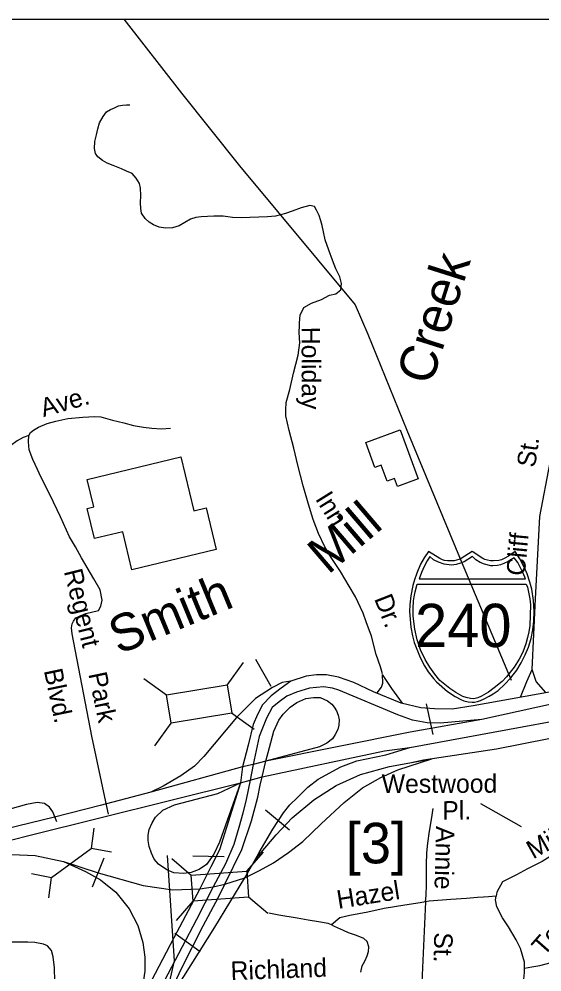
# Model space of a CAD drawing. Extents: x 925297 to 940193, y 663541 to 689899.
# Drawn here: x 929084 to 929507, y 688730 to 689501 of the extents above; entities that cross this region are included whole.
import ezdxf

# ---------------------------------------------------------------- set-up
doc = ezdxf.new("R2010")
doc.units = 0
doc.layers.add('Default', color=7, linetype='Continuous')
doc.layers.add('Sheet Title CELL', color=7, linetype='Continuous')

msp = doc.modelspace()

# ---------------------------------------------------------------- linework, layer by layer
at = {"layer": 'Default'}
for p, q in [((929252.05, 688962.28), (929265.27, 688980.66)), ((929275.13, 688983.38), (929287.52, 688961.33)), ((929184.73, 688967.62), (929203.11, 688954.4)), ((929413.23, 688947.08), (929418.64, 688922.38)), ((929255.7, 688939.94), (929274.07, 688926.72)), ((929193.62, 688913.17), (929206.84, 688931.55)), ((929156.03, 688857.77), (929154.68, 688864.04)), ((929283.17, 688861.25), (929302.69, 688845.17)), ((929144.14, 688846.59), (929142.01, 688830.07)), ((929109.96, 688806.69), (929142.01, 688830.07)), ((929158.39, 688827.05), (929142.01, 688830.07)), ((929267.97, 688811.6), (929281.42, 688827.17)), ((929152.28, 688822.13), (929142.84, 688798.67)), ((929207.44, 688821.86), (929223.01, 688808.41)), ((929224.33, 688824.24), (929249.61, 688823.5)), ((929093.58, 688809.71), (929109.96, 688806.69)), ((929107.83, 688790.17), (929109.96, 688806.69)), ((929229.97, 688797.34), (929240.68, 688799)), ((929211.1, 688771.84), (929224.55, 688787.41)), ((929269.47, 688791.08), (929285.05, 688777.63)), ((929412.85, 688786.82), (929409.51, 688715.72)), ((929209.72, 688761.43), (929230.21, 688746.61))]:
    msp.add_line(p, q, dxfattribs=at)
for points in [[(929168.36, 689501.34), (929215.26, 689441.28), (929262.13, 689382.59), (929355.71, 689269.93), (929365.93, 689246.36), (929397.72, 689168.54), (929441.55, 689062.65), (929482.15, 688966.28)], [(929378.04, 688971.41), (929376.26, 688977.04), (929372.78, 688987.01), (929369.08, 689001.83), (929364.67, 689013.56), (929362.13, 689020.41), (929356.02, 689033.71), (929350.94, 689042.25), (929343.9, 689054.19), (929336.31, 689065.66), (929331.23, 689074.32), (929326.05, 689085.09), (929321.75, 689096.33), (929317.59, 689109.43), (929313.73, 689123.64), (929309.48, 689140.37), (929305.99, 689154.01), (929302.43, 689168.45), (929299.51, 689180.23), (929299.72, 689185.02), (929299.99, 689190.97), (929302.79, 689201.42), (929305.74, 689214.77), (929309.71, 689229.41), (929310.91, 689239.34), (929310.41, 689247.71), (929310.57, 689253.41), (929310.63, 689255.43), (929311.3, 689261.76), (929314.3, 689267.78), (929320.31, 689271.28), (929328.45, 689274.3), (929335.11, 689277.82), (929340.19, 689279.06), (929344.25, 689282.11), (929344.75, 689287.2), (929343.23, 689292.63), (929340.24, 689299.18), (929337.45, 689306.19), (929334.42, 689314.17), (929331.4, 689322.65), (929330.01, 689329.2), (929329.08, 689334.15), (929327.99, 689338.13), (929326.6, 689342.44), (929324.57, 689346.81), (929322.91, 689349.53), (929319.03, 689350.55), (929312.06, 689348.53), (929304.71, 689345.84), (929299.49, 689344.09), (929291.28, 689341.85), (929284.87, 689341.31), (929263.56, 689340.46), (929256.33, 689340.87), (929248.95, 689341.83), (929241.46, 689341.87), (929230.94, 689341.26), (929226.71, 689340.63), (929222.41, 689339.34), (929213.21, 689334.08), (929207.82, 689332.3), (929202.1, 689332.12), (929196.96, 689332.98), (929192.58, 689334.69), (929189.07, 689337.04), (929185.62, 689339.88), (929182.85, 689344.2), (929182.14, 689348.06), (929181.96, 689352.72), (929182.18, 689358.63), (929181.85, 689364.56), (929181.2, 689368.28), (929178.49, 689372.48), (929175.16, 689376.38), (929170.58, 689378.13), (929166.58, 689380.14), (929159.88, 689382.91), (929154.91, 689384.59), (929151.29, 689386.82), (929147.4, 689389.82), (929145.5, 689392.59), (929144.8, 689396.71), (929144.87, 689402.23), (929144.88, 689402.23), (929146.21, 689407.72), (929147.31, 689412.38), (929148.8, 689417.24), (929151.66, 689422.55), (929154.53, 689426.37), (929157.75, 689428.1), (929160.8, 689429.59), (929164.16, 689430.98), (929167.39, 689431.63), (929170.63, 689431.8), (929173.36, 689431.84)], [(929499.18, 688974.92), (929501.93, 689032.24), (929505.34, 689098.74), (929513.58, 689142.43), (929524.71, 689167.77), (929536.62, 689179.25), (929545.81, 689184.49), (929556.93, 689190.11)], [(929091.59, 689164.22), (929092.87, 689166.73), (929095.19, 689168.5), (929099.4, 689170.93), (929106.48, 689173.92), (929113.34, 689176.02), (929123.07, 689178.12), (929135.35, 689179.12), (929144.97, 689179.67), (929149.84, 689179.34), (929159.25, 689176.79), (929168.54, 689174.47), (929176.17, 689172.48), (929184.36, 689171.04), (929191.11, 689170.16), (929198.96, 689169.72), (929206.26, 689170.16)], [(929091.59, 689164.22), (929086.94, 689162.68), (929082.03, 689159.98), (929076.97, 689156.13), (929070.78, 689150.36), (929062.73, 689145.3), (929053.32, 689140.42), (929045.08, 689137.59), (929039.9, 689135.71)], [(929154.68, 688864.04), (929142.45, 688920.9), (929126.58, 689003.68), (929126.06, 689008.76), (929126.5, 689011.85), (929127.61, 689013.96), (929129.49, 689016.72), (929132.12, 689017.89), (929137.68, 689020.15), (929147.85, 689022.69), (929149.85, 689026.12), (929150.84, 689030.99), (929149.32, 689039.3), (929144.09, 689048.25), (929134.14, 689065.31), (929129.28, 689074.14), (929124.51, 689082.32), (929117.21, 689098.58), (929108.8, 689115.95), (929101.17, 689130.88), (929098.51, 689136.75), (929094.75, 689144.93), (929091.76, 689152.79), (929091.32, 689159.2), (929091.59, 689164.22)], [(929489.63, 688952.5), (929494.84, 688965.1), (929499.18, 688974.92)], [(929510.24, 688956.45), (929502.37, 688965.24), (929499.18, 688974.92)], [(929303.7, 688965.55), (929296.72, 688964.48), (929288.77, 688960.39), (929275.02, 688951.36), (929265.56, 688942.11), (929259.76, 688936.09), (929233.11, 688904.49), (929225.7, 688896.75), (929214.64, 688888.79), (929200.35, 688880.41), (929190.42, 688875.58)], [(929303.7, 688965.55), (929295.75, 688959.75), (929287.69, 688953.62), (929280.82, 688946.31), (929276.73, 688938.57), (929273.3, 688930.29), (929269, 688913.73), (929264.67, 688896.19)], [(929606.92, 688969.72), (929604.98, 688969.65), (929573.53, 688965.31), (929525.09, 688958.79), (929451.35, 688945.41), (929434.36, 688942.88), (929419.9, 688943.06), (929409.05, 688943.78), (929392.97, 688947.58), (929370.73, 688956.81), (929354.83, 688964.4), (929342.38, 688968.78), (929332.5, 688970.5), (929324.54, 688970.71), (929316.06, 688969.53), (929303.7, 688965.55)], [(929373.49, 688956.02), (929377.22, 688960.54), (929378.21, 688963.79), (929378.04, 688970.98)], [(929394.2, 688947.64), (929385.38, 688959.68), (929378.04, 688970.98)], [(929621.29, 688970.27), (929458.27, 688934.53)], [(929458.27, 688934.53), (929424.65, 688931.46), (929414.16, 688931.64), (929402.24, 688933.99), (929390.31, 688938.33), (929342.59, 688958.23), (929337.48, 688959.88), (929330.12, 688960.94), (929318.86, 688959.7), (929308.38, 688956.62), (929300.41, 688953.38), (929294.34, 688948.83), (929288.63, 688944.1), (929283.92, 688935.6), (929277.91, 688920.75), (929273.08, 688898.02)], [(929400.16, 688911.9), (929605.34, 688949.58), (929647.6, 688958.63)], [(929283.32, 688900.7), (929286.35, 688911.85), (929290.01, 688925.04), (929293.91, 688933.83), (929297.57, 688938.83), (929303.06, 688944.45), (929308.55, 688948.11), (929315.87, 688951.41), (929321.97, 688952.38), (929327.46, 688952.14), (929333.32, 688949.48)], [(929333.32, 688949.48), (929336.85, 688946.89), (929338.8, 688944.33), (929340.76, 688941.52), (929342.1, 688937.98), (929342.71, 688934.19), (929342.46, 688929.92), (929341.73, 688926.38), (929339.66, 688922.35), (929337.34, 688918.81), (929332.95, 688915.39), (929326.85, 688912.46), (929283.32, 688900.7)], [(929458.27, 688934.53), (929400.26, 688924.11), (929283.32, 688900.7)], [(929402.43, 688899.91), (929411.12, 688901.71), (929470.24, 688910.78), (929534.53, 688923.46), (929536.63, 688924.03)], [(929275.08, 688821.48), (929278.13, 688826.84), (929289.16, 688845.73), (929297.7, 688859.03), (929302.77, 688865.51), (929309.12, 688871.36), (929317.46, 688879.71), (929325.8, 688886.26), (929344.05, 688896.14), (929357.21, 688900.97), (929380.51, 688905.89), (929400.16, 688911.9)], [(929280.5, 688888.12), (929379.41, 688908.98), (929400.16, 688911.9)], [(929266.51, 688806.41), (929278.27, 688812.23), (929289.59, 688818.49), (929301.8, 688826.83), (929313.41, 688835.77), (929328.31, 688850.08), (929346.78, 688867.36), (929361.67, 688879.28), (929376.59, 688887.63), (929390.46, 688893.74), (929417.93, 688902.6)], [(929275.08, 688821.48), (929291.8, 688841.19), (929304.87, 688854.94), (929322.3, 688869.36), (929340.4, 688881.1), (929360.17, 688889.82), (929383.62, 688896.33), (929417.93, 688902.6)], [(929264.67, 688896.19), (929190.42, 688875.58)], [(929264.67, 688896.19), (929262.95, 688883.29)], [(929273.08, 688898.02), (929264.67, 688896.19)], [(929273.08, 688898.02), (929270.84, 688885.3)], [(929283.32, 688900.7), (929273.08, 688898.02)], [(929280.5, 688888.12), (929283.32, 688900.7)], [(929250.18, 688801.15), (929264.03, 688829.19), (929271.82, 688852.34), (929276.83, 688871.74), (929278.91, 688881.31), (929280.5, 688888.12)], [(929270.84, 688885.3), (929280.5, 688888.12)], [(929027.74, 688824.35), (929091.51, 688840.54), (929262.95, 688883.29)], [(929262.95, 688883.29), (929245.94, 688835.24), (929241.44, 688825.45), (929235.5, 688817.13), (929229.56, 688812.97), (929223.02, 688810.59), (929216.69, 688809.8), (929208.96, 688810.4), (929203.22, 688812.77), (929196.49, 688817.33), (929193.12, 688821.49), (929190.78, 688826.24), (929188.87, 688831.77), (929188.23, 688836.45), (929188.23, 688840.92), (929188.87, 688845.39), (929191.34, 688850.82), (929194.11, 688855.37), (929200.05, 688861.12), (929209.35, 688865.39), (929244.57, 688874.69), (929262.95, 688883.29)], [(929262.95, 688883.29), (929245.85, 688828.9), (929239.02, 688815.13), (929229.97, 688797.34)], [(929270.84, 688885.3), (929267.43, 688869.63), (929264.84, 688858.67), (929261.65, 688847.01), (929257.65, 688833.35), (929250.79, 688817.68), (929240.68, 688799)], [(929262.95, 688883.29), (929270.84, 688885.3)], [(929190.42, 688875.58), (929149.29, 688864.98), (929112.36, 688855.44), (929052.19, 688840.84), (929001.1, 688828.77), (928863.79, 688792.71), (928727.82, 688759.49), (928686.82, 688753.06), (928655.56, 688749.51), (928625.66, 688747.58), (928584.13, 688746.27), (928553.43, 688746.59)], [(929114.22, 688851.67), (929110.87, 688859.75), (929108.23, 688863.64), (929104.25, 688866.47), (929098.22, 688867.29), (929089.64, 688865.56), (929082.78, 688863.79), (929076.09, 688861.93), (929072.45, 688860.92)], [(929457.14, 688866.48), (929490.26, 688847.89)], [(929581.65, 688866.44), (929580.92, 688866.03), (929568.37, 688858.13), (929557.96, 688851.93), (929545.47, 688843.03), (929541.21, 688840.61), (929535.96, 688837.63), (929527.86, 688832.08), (929521.92, 688828.59), (929517.23, 688825.82), (929507.25, 688819.65), (929495.21, 688813.72), (929486.39, 688808.82), (929474.98, 688803.19), (929470.63, 688794.83), (929469.91, 688791.45)], [(929412.85, 688786.82), (929413.37, 688791.91), (929413.6, 688800.69), (929413.45, 688809.36), (929413.47, 688817.23), (929413.69, 688826.46), (929414.51, 688834.27), (929416, 688844.04), (929417.58, 688853.66), (929418.89, 688862.56)], [(929027.74, 688824.35), (929049.36, 688824.03), (929077.63, 688825.22), (929096.68, 688824.32), (929119.59, 688819.56)], [(929119.59, 688819.56), (929137.45, 688811.52), (929149.65, 688804.67), (929161.85, 688794.84), (929172.86, 688781.14), (929179.71, 688767.74), (929183.88, 688754.04), (929185.36, 688742.13), (929185.46, 688730.85), (929184.09, 688721.85), (929179.67, 688708.57), (929170.37, 688686.19)], [(929119.59, 688819.56), (929147.74, 688810.36), (929184.05, 688800.24), (929208.16, 688796.66), (929229.97, 688797.34)], [(929131.57, 688454.71), (929133.41, 688495.05), (929139.69, 688536.07), (929153.55, 688576.4), (929172.02, 688622.58), (929191.38, 688660.69), (929209.61, 688739.05), (929203.87, 688824.44)], [(929266.51, 688806.41), (929275.08, 688821.48)], [(929197.77, 688696.08), (929242.19, 688766.42), (929266.51, 688806.41)], [(929250.18, 688801.15), (929266.51, 688806.41)], [(929240.68, 688799), (929227.23, 688772.53), (929180.84, 688684.11), (929164.1, 688653.95), (929138.06, 688598.39), (929121.88, 688556.31), (929112.47, 688532.84)], [(929229.97, 688797.34), (929209.05, 688757.78), (929187.54, 688717.1), (929177.86, 688697.73), (929170.37, 688686.19)], [(929197.77, 688696.08), (929215.22, 688732.92), (929232.57, 688767.49), (929244.99, 688790.68), (929250.18, 688801.15)], [(929240.68, 688799), (929250.18, 688801.15)], [(929412.85, 688786.82), (929408.4, 688786.02), (929395.92, 688784.09), (929379.34, 688781.39), (929366.03, 688778.6), (929351.38, 688775.73), (929343.46, 688773.83), (929336.58, 688768.17)], [(929469.91, 688791.45), (929463.87, 688791.03), (929459.8, 688790.58), (929454.8, 688790.47), (929446, 688789.67), (929433.32, 688788.89), (929415.65, 688787.32), (929412.85, 688786.82)], [(929492.92, 688733.26), (929492.8, 688738.2), (929489.69, 688749.04), (929486.18, 688756.25), (929480.04, 688766.57), (929475.14, 688774.02), (929470.57, 688782.73), (929469.29, 688788.46), (929469.91, 688791.45)], [(929336.58, 688768.17), (929333.98, 688769.42), (929326.18, 688770.85), (929317.67, 688772.01), (929308.83, 688773.63), (929293.88, 688776.15), (929285.82, 688777.66)], [(929360.24, 688729.89), (929361.44, 688735.06), (929363.49, 688738.76), (929365.37, 688743.13), (929366.52, 688746.73), (929366.78, 688750.47), (929365.55, 688754.9), (929362.92, 688757.17), (929356.86, 688759.64), (929350.44, 688761.79), (929346.42, 688763.68), (929339.14, 688766.94), (929336.58, 688768.17)], [(929108.94, 688663.7), (929111.3, 688666.43), (929112.62, 688671.03), (929112.14, 688679.96), (929112.31, 688697.45), (929112.37, 688710.68), (929112.61, 688722.6), (929112.33, 688733.46), (929111.33, 688742.29), (929109.75, 688747.64), (929106.64, 688751.17), (929103.33, 688752.74), (929096.45, 688754.02), (929090.6, 688754.27), (929084.08, 688754.39), (929078.13, 688754.15), (929073.55, 688753.81), (929070.57, 688753.47), (929068.16, 688752.56), (929066.69, 688750.55), (929066.4, 688749.72)], [(929470.4, 688664.68), (929470.79, 688666.32), (929472.7, 688672.6), (929476.64, 688684.36), (929480.67, 688693.76), (929487.77, 688708.46), (929491.81, 688718.81), (929493, 688729.64), (929492.92, 688733.26)], [(929492.92, 688733.26), (929498.96, 688734.38), (929505.36, 688735.49), (929514.55, 688737.73)]]:
    msp.add_lwpolyline(points, dxfattribs=at)
for points in [[(929392.09, 689168.89), (929406.92, 689129.18), (929390.17, 689122.93), (929387.7, 689129.55), (929381.67, 689127.29), (929376.79, 689140.39), (929371.8, 689138.53), (929364.34, 689158.52)], [(929138.84, 689128.83), (929214.71, 689147.15), (929225.26, 689103.46), (929235.14, 689105.85), (929243.28, 689072.15), (929174.94, 689055.65), (929167.51, 689086.4), (929144.74, 689080.9), (929138.84, 689105.33), (929144.2, 689106.62)], [(929450.4, 688948.36), (929452.3, 688948.54), (929454.84, 688949.03), (929457.32, 688949.85), (929460.14, 688951.09), (929464.31, 688953.4), (929467.66, 688955.37), (929471.53, 688957.96), (929476.75, 688962.71), (929481.96, 688968.19), (929486.56, 688974.4), (929490.21, 688980.2), (929493.43, 688986.83), (929496.11, 688993.01), (929498.25, 689000.08), (929499.66, 689006.93), (929500.37, 689014.06), (929500.85, 689021.98), (929500.31, 689030.89), (929498.76, 689040), (929497.31, 689045.67), (929495.1, 689052.46), (929493.3, 689056.79), (929489.13, 689064.48), (929485.39, 689070.4), (929479.94, 689066.57), (929476.39, 689064.68), (929474.22, 689063.71), (929471.99, 689063.27), (929467.89, 689062.77), (929465.31, 689062.89), (929462.92, 689063.43), (929460.9, 689063.87), (929459.25, 689064.68), (929450.4, 689070.4), (929441.55, 689064.68), (929439.69, 689063.83), (929437.79, 689063.43), (929435.96, 689062.92), (929432.93, 689062.77), (929430.62, 689062.85), (929428.24, 689063.27), (929426.37, 689063.66), (929424.27, 689064.68), (929415.24, 689070.4), (929411.7, 689065.26), (929408.8, 689060.18), (929405.73, 689052.99), (929403.82, 689047.43), (929402.46, 689042.85), (929400.79, 689034.46), (929399.93, 689027.15), (929399.78, 689021.98), (929400.73, 689009.08), (929402.14, 689002.21), (929403.58, 688996.65), (929408.36, 688984.64), (929411.94, 688977.92), (929415.02, 688973.08), (929419.34, 688967.65), (929421.68, 688965.06), (929430.64, 688957.23), (929436.62, 688953.14), (929441.4, 688950.56), (929443.65, 688949.7), (929447.17, 688948.72)], [(929416.32, 689066.25), (929414.12, 689062.87), (929411.58, 689058.3), (929409.55, 689053.57), (929407.48, 689048.33), (929493.79, 689048.3), (929491.79, 689052.79), (929489.63, 689057.29), (929487.38, 689061.41), (929484.64, 689065.39), (929479.8, 689062.34), (929476.28, 689060.67), (929473.44, 689059.69), (929471.04, 689059.15), (929467.32, 689058.86), (929465.66, 689058.96), (929460.47, 689060.13), (929456.96, 689061.57), (929453.62, 689063.8), (929450.92, 689066.34), (929444.08, 689062.2), (929441.05, 689060.87), (929437.56, 689059.98), (929433.74, 689059.5), (929427.85, 689060.13), (929423.24, 689061.73), (929419.26, 689063.8)], [(929494.3, 689044.04), (929495.23, 689041.61), (929496.5, 689036.2), (929497.17, 689032.03), (929497.85, 689027.23), (929497.62, 689019), (929497.22, 689010.49), (929496.43, 689005.44), (929495.39, 689000.86), (929493.96, 688995.77), (929491.65, 688989), (929488.47, 688983.27), (929484.49, 688976.9), (929480.2, 688971.33), (929478.33, 688969.02), (929474.79, 688965.28), (929468.35, 688960.11), (929463.64, 688956.59), (929458.01, 688953.27), (929455.14, 688951.99), (929451.81, 688951.29), (929449.07, 688951.49), (929445.74, 688952.37), (929443.06, 688953.11), (929437.17, 688956.29), (929432.4, 688959.48), (929424.44, 688966), (929420.16, 688971.03), (929416.14, 688976.9), (929412.57, 688982.92), (929408.76, 688990.85), (929406.06, 688998.83), (929404.11, 689007.45), (929402.79, 689017.98), (929402.64, 689024.39), (929403.03, 689030.56), (929403.62, 689033.79), (929404.4, 689037.81), (929405.97, 689044)], [(929203.11, 688954.4), (929252.04, 688962.39), (929255.77, 688939.53), (929206.84, 688931.55)], [(929223.01, 688808.41), (929267.96, 688811.7), (929269.5, 688790.7), (929224.55, 688787.41)]]:
    msp.add_lwpolyline(points, close=True, dxfattribs=at)
at = {"layer": 'Sheet Title CELL'}
msp.add_lwpolyline([(927148.43, 689501.34), (930192.06, 689501.34), (930192.06, 687400.3), (927148.43, 687400.3)], close=True, dxfattribs=at)

# ---------------------------------------------------------------- texts
at = {"layer": 'Default'}
for s, height, rotation, p in [('Creek', 30, 72.44743, (929417.33, 689204.02)), ('Holiday', 15, 270.09247, (929312.41, 689252.27)), ('Ave.', 15, 15.9152, (929103.33, 689179.1)), ('St.', 15, 81.82693, (929501.44, 689137.92)), ('Inn', 15, 302.01003, (929323.05, 689113.04)), ('Mill', 30, 40.52039, (929333.83, 689051.15)), ('Cliff', 15, 84.57547, (929493.03, 689050.28)), ('Regent', 15, 283.86936, (929119.79, 689054.43)), ('Smith', 30, 22.45649, (929164.24, 688986.82)), ('Dr.', 15, 291.4453, (929370.98, 689032.3)), ('Blvd.', 15, 281.75183, (929103.64, 688974.14)), ('Park', 15, 281.75183, (929139.64, 688971.38)), ('Westwood', 15, 0.15812, (929377.27, 688874.96)), ('Pl.', 15, 0.55106, (929426.36, 688853.34)), ('Mill', 15, 29.28828, (929499.89, 688821.12)), ('Annie', 15, 268.47965, (929421.35, 688848.25)), ('Toxaway', 15, 48.70238, (929508.67, 688742.28)), ('Hazel', 15, 9.15294, (929342.12, 688781.16)), ('St.', 15, 268.65049, (929419.86, 688762.4)), ('Richland', 15, 2.04511, (929255.15, 688723.54))]:
    msp.add_text(s, height=height, rotation=rotation, dxfattribs=at).set_placement(p)
for s, height, p in [('240', 35, (929404.28, 688993.11)), ('[3]', 32.808, (929348.2, 688818.04))]:
    msp.add_text(s, height=height, dxfattribs=at).set_placement(p)

doc.saveas('drawing.dxf')
